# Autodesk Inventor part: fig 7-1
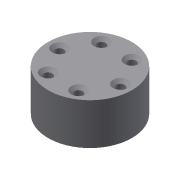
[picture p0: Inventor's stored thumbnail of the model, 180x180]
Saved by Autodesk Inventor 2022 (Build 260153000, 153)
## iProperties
Created: 2004-05
Part Number: fig 7-1
Document SubType Name: Modeling
Designer: CADCIM Technologies
Manufacturer: Standard
Standards Organization: Custom
Density: 1 g/cm^3
Material: Generic
Appearance: Default
Author: CADCIM Technologies
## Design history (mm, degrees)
sketch "Sketch1"
  geometry: C1 r 17.175 at (0, 0)
  constraints: 1 centre point
extrude "Extrusion1" new body sketch "Sketch1" distance "d0" = 17; taper "d1" = 0 deg
sketch "Sketch2"
  geometry: 1 further point
hole "Hole1" sketch "Sketch2" at (12.571, -0.074) diameter "d2" = 3.5; stored, may be unused: countersink angle "d6" = 90 deg, drill point angle "d8" = 118 deg; dims "d3" = 6, "d4" = 6, "d5" = 2, "d7" = 8
pattern_circular "Circular Pattern1" dims angle "d11" = 360 deg
body "Solid1"
